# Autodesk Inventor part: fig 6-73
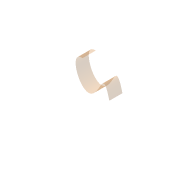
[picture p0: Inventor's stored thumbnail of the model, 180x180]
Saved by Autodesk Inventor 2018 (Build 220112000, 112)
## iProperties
Shininess: 64.0
Length Units: 11269
Angle Units: 11279
Time Units: 11290
Mass Units: 11283
Length Display Precision: 3
Angle Display Precision: 2
Compacted: True
Part Number: fig 6-73
Document SubType Name: Modeling
Created: 2002-12
Designer: deepak
Density: 1 g/cm^3
Material: Generic
Appearance: Default
Density: 0.0
Volumn: 0.0
Area: 0.0
PropertySet Name: Model Information
Control State: 0
Master: False
Checked Out: False
Author: deepak
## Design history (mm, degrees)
sketch "Sketch1"
  geometry: 5 further points
  constraints: 5 other
extrude_surface "ExtrusionSrf1" sketch "Sketch1" dims "d0" = 20, "d1" = 0
body "Srf1"
